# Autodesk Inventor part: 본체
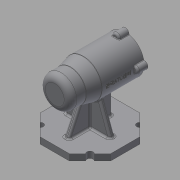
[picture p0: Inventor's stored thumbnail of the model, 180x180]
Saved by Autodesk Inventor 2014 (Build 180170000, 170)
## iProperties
Created: 2019-12
Part Number: 본체
Material: Aluminum 6061
Document SubType Name: Modeling
Designer: kh
Density: 2.71 g/cm^3
Appearance: Default
Mass: 727.794 g
Surface Area: 716.602 cm^2
Volume: 268.559 cm^3
Author: kh
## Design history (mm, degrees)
sketch "Sketch2"
  geometry: L1 (-56, 0)-(56, 0); L2 (-11, 30)-(56, 30); L3 (-56, 25)-(-31, 25); L4 (-31, 25)-(-11, 30); L5 (-56, 25)-(-56, 0); L6 (-13, 24)-(41, 24); L7 (41, 21)-(56, 21); L8 (41, 21)-(41, 24); L9 (56, 21)-(56, 30); L10 (-13, 21)-(-25, 21); L11 (-13, 21)-(-13, 24); L12 (-25, 17.5)-(-43, 17.5); L13 (-25, 17.5)-(-25, 21); L14 (-43, 16)-(-47, 16); L15 (-43, 16)-(-43, 17.5); L16 (-47, 10.5)-(-50, 10.5); L17 (-47, 10.5)-(-47, 16); L18 (-50, 10.5)-(-50, 0); 2 further points
  constraints: 36 end point, 12 perpendicular, 8 vertical alignment, 4 parallel, 2 coincident, 1 horizontal, 1 midpoint, 1 point on line
  dimensions: "d0" = 112 distance of L1.start L1.end; "d1" = 67 distance of L2.start L2.end; "d2" = 60 diameter of L2 L1; "d3" = 25 distance of L3.start L3.end; "d4" = 50 diameter of L3 L1; "d5" = 54 distance of L6.start L6.end; "d6" = 48 diameter of L6 L1; "d7" = 15 distance of L7.start L7.end; "d8" = 42 diameter of L7 L1; "d9" = 12 distance of L10.start L10.end; "d10" = 42 diameter of L10 L1; "d11" = 18 distance of L12.start L12.end; "d12" = 35 diameter of L12 L1; "d14" = 4 distance of L14.start L14.end; "d15" = 32 diameter of L14 L1; "d16" = 3 distance of L16.start L16.end; "d17" = 21 diameter of L16 L1
revolve "Revolution1" sketch "Sketch2" stored, may be unused: angle "d19" = 90 deg
fillet "Fillet1" dims "d22" = 3, "d23" = 0.3
workplane "Work Plane1"
sketch "Sketch4"
  geometry: L1 (0, 0)-(0, 30); C1 r 21 at (0, 0) reference; C2 r 6 at (0, 30); 1 further point
  constraints: 2 end point, 1 centre point, 1 coincident, 1 vertical, 1 vertical alignment, 1 other
  dimensions: "d24" = 12 diameter of C2
extrude "Extrusion2" join sketch "Sketch4" distance "d25" = 16; taper "d26" = 0 deg
fillet "Fillet2" dims "d27" = 3
fillet "Fillet3" dims "d28" = 1
pattern_circular "Circular Pattern1" dims "d30" = 360 deg
hole "Hole1" diameter "d34" = 3.242; stored, may be unused: countersink angle "d38" = 90 deg, drill point angle "d40" = 118 deg; dims "d32" = 10, "d33" = 10, "d35" = 8, "d36" = 4, "d37" = 2, "d39" = 11
pattern_circular "Circular Pattern2" dims angle "d42" = 360 deg
workplane "Work Plane2"
sketch "Sketch5"
  geometry: L1 (-6.771, 56)-(-29.226, 56) reference; L2 (29.226, 56)-(6.771, 56) reference; L3 (23.196, 56)-(56, 23.196); L4 (56, 23.196)-(56, -23.196); L5 (56, -23.196)-(23.196, -56); L6 (23.196, -56)-(-23.196, -56); L7 (-23.196, -56)-(-56, -23.196); L8 (-56, -23.196)-(-56, 23.196); L9 (-56, 23.196)-(-23.196, 56); L10 (-23.196, 56)-(23.196, 56); 2 further points
  constraints: 16 end point, 1 coincident, 1 collinear, 1 horizontal, 17 other
extrude "Extrusion3" join sketch "Sketch5" distance "d45" = 10; taper "d46" = 0 deg
sketch "Sketch6"
  geometry: L1 (56, 23.196)-(23.196, 56) reference; L2 (56, -23.196)-(56, 23.196) reference; L3 (0, 0)-(56, 0); L4 (0, 0)-(39.598, 39.598); C1 r 5 at (39.598, 39.598)
  constraints: 4 end point, 2 midpoint, 1 centre point, 1 coincident, 1 perpendicular
  dimensions: "d47" = 10 diameter of C1
extrude "Extrusion4" cut sketch "Sketch6" stored distance "d48" = 10; taper "d49" = 0 deg
pattern_circular "Circular Pattern3" dims angle "d51" = 360 deg
sketch "Sketch7"
  geometry: L1 (-56, -80)-(-56, -70) reference; L2 (56, -80)-(56, -70) reference; L3 (56, -70)-(43.134, -70) reference; L4 (23.196, -70)-(-23.196, -70) reference; L5 (-43.134, -70)-(-56, -70) reference; L6 (34.598, -70)-(43.134, -70) reference; L7 (36.062, -70)-(23.196, -70) reference; L8 (-43.134, -70)-(-34.598, -70) reference; L9 (-23.196, -70)-(-36.062, -70) reference; L10 (0, 0)-(0, -70); L11 (-36, -70)-(-18.979, -23.234); L12 (36, -70)-(18.979, -23.234); L13 (-36, -70)-(36, -70); A1 r 30 centre (0, 0) between (-18.979, -23.234) and (18.979, -23.234); 1 further point
  constraints: 8 end point, 2 point on circle, 2 symmetric about line, 1 centre point, 1 coincident, 1 collinear, 1 midpoint, 1 point on line, 2 other
  dimensions: "d55" = 110 deg angle of L5 L11; "d56" = 20 distance from line of L11.start L1
extrude "Extrusion5" join sketch "Sketch7" stored distance "d57" = 8; taper "d58" = 0 deg
sketch "Sketch8"
  geometry: L1 (-56, -80)-(-56, -70) reference; L2 (56, -80)-(56, -70) reference; L3 (56, -70)-(43.134, -70) reference; L4 (34.598, -70)-(43.134, -70) reference; L5 (36.062, -70)-(23.196, -70) reference; L6 (23.196, -70)-(-23.196, -70) reference; L7 (-23.196, -70)-(-36.062, -70) reference; L8 (-43.134, -70)-(-56, -70) reference; L9 (-43.134, -70)-(-34.598, -70) reference; L10 (-56, -25)-(-31, -25) reference; L11 (-31, -25)-(-11, -30) reference; L12 (-11, -30)-(39, -30) reference; L13 (-38, -70)-(-17.308, -25.627); L14 (31, -25.627)-(31, -70); L15 (-38, -70)-(31, -70); L16 (-17.308, -25.627)-(31, -25.627); 3 further points
  constraints: 8 end point, 6 point on line, 2 perpendicular, 1 parallel
  dimensions: "d60" = 115 deg angle of L8 L13; "d61" = 18 distance from line of L1 L13.start; "d62" = 25 distance between parallel lines of L2 L14
extrude "Extrusion6" join sketch "Sketch8" stored distance "d63" = 8; taper "d64" = 0 deg
fillet "Fillet4" dims "d65" = 3, "d66" = 10
fillet "Fillet5" dims "d67" = 3
chamfer "Chamfer1" distance "d68" = 1; stored, may be unused: second distance "d69" = 2, angle "d70" = 45 deg
sketch "Sketch9"
  geometry: L1 (-33.131, 30)-(16.5, 30) reference; L2 (33.5, 6.771)-(33.5, 29.226) reference; L3 (33.5, -29.226)-(33.5, -6.771) reference; 2 further points
  constraints: 1 horizontal alignment, 1 other
  dimensions: "d71" = 41 distance from line of L2 point (-7.5, 0)
emboss "Emboss1" sketch "Sketch9" dims "d0" = 112, "d1" = 67, "d2" = 60, "d3" = 25, "d4" = 50, "d5" = 54, "d6" = 48, "d7" = 15, "d8" = 42, "d9" = 12, "d10" = 42, "d11" = 18, "d12" = 35, "d14" = 4, "d15" = 32, "d16" = 3, "d17" = 21, "d72" = 0.5, "d73" = 0
fillet "Fillet6" dims "d76" = 3
body "Solid1"
